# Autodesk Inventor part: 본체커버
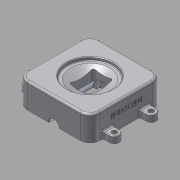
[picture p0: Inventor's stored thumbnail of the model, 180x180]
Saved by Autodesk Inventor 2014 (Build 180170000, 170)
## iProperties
Created: 2018-01
Part Number: 본체커버
Material: 알루미늄 6061
Document SubType Name: Modeling
Designer: mduedu
Density: 1 g/cm^3
Appearance: Aluminum - Flat
Author: mduedu
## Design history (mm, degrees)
sketch "스케치1"
  geometry: L1 (55, 55)-(-55, 55); L2 (-55, 55)-(-55, -55); L3 (-55, -55)-(55, -55); L4 (55, -55)-(55, 55); L5 (55, 55)-(-55, -55); L6 (-55, 55)-(55, -55); 1 further point
  constraints: 12 end point, 2 midpoint, 2 parallel, 1 horizontal, 1 perpendicular
  dimensions: "d0" = 110 distance of L3.end L2.end; "d1" = 110 distance of L2.end L1.end
extrude "돌출1" new body sketch "스케치1" distance "d2" = 38; taper "d3" = 0 deg
sketch "스케치2"
  geometry: L1 (-55, 55)-(55, 55) reference; L2 (-55, -55)-(-55, 55) reference; L3 (55, -55)-(-55, -55) reference; L4 (55, 55)-(55, -55) reference; L5 (0, 55)-(7.5, 55); L6 (7.5, 55)-(7.5, 36); L7 (7.5, 36)-(0, 36); L8 (0, 36)-(0, 55); L9 (0, 36)-(16, 36); L10 (16, 36)-(16, 22); L11 (16, 22)-(0, 22); L12 (0, 22)-(0, 36); L13 (0, 22)-(20, 22); L14 (20, 22)-(20, -25); L15 (20, -25)-(0, -25); L16 (0, -25)-(0, 22); L17 (0, -25)-(15, -25); L18 (15, -25)-(15, -30); L19 (15, -30)-(0, -30); L20 (0, -30)-(0, -25); 1 further point
  constraints: 32 end point, 8 parallel, 4 horizontal, 4 perpendicular, 1 midpoint
  dimensions: "d4" = 15 diameter of L6 L8; "d6" = 32 diameter of L10 L12; "d7" = 40 diameter of L14 L16; "d8" = 30 diameter of L18 L20; "d9" = 5 distance of L17.end L18.end; "d10" = 47 distance of L13.end L14.end; "d11" = 14 distance of L9.end L10.end; "d12" = 19 distance of L5.end L6.end
revolve "회전1" sketch "스케치2" stored, may be unused: angle "d13" = 90 deg
fillet "모깎기1" dims "d14" = 1
fillet "모깎기2" dims "d15" = 15
fillet "모깎기3" dims "d16" = 3
sketch "스케치3"
  geometry: L1 (-15, -17)-(15, -17); L2 (15, -17)-(15, 20); L3 (15, 20)-(-15, 20); L4 (-15, 20)-(-15, -17); L5 (-19, -22)-(19, -22) reference; L6 (19, 25)-(-19, 25) reference; 2 further points
  constraints: 8 end point, 2 parallel, 1 horizontal, 1 midpoint, 1 perpendicular, 1 vertical alignment
  dimensions: "d17" = 5 distance between parallel lines of L1 L5; "d18" = 5 distance between parallel lines of L6 L3; "d19" = 37 distance of L3.end L1.start (derived); "d20" = 30 distance between parallel lines of L2 L4
extrude "돌출2" cut sketch "스케치3" stored distance "d21" = 38; taper "d22" = 0 deg
fillet "모깎기4" dims "d23" = 3
sketch "스케치4"
  geometry: L1 (38, 35)-(33, 35); L2 (33, 35)-(33, 30); L3 (33, 30)-(26, 15); L4 (26, 15)-(26, 0); L5 (26, 0)-(38, 0); L6 (38, 0)-(38, 35); L7 (38, 40)-(38, -40) reference; 1 further point
  constraints: 12 end point, 2 parallel, 1 collinear, 1 horizontal, 1 horizontal alignment, 1 perpendicular
  dimensions: "d24" = 5 distance of L1.start L1.end; "d26" = 70 diameter of L1 L5; "d28" = 60 diameter of L2.end L5; "d29" = 30 diameter of L3.end L5; "d30" = 7 horizontal distance of L2.end L3.end
revolve "회전2" sketch "스케치4" stored, may be unused: angle "d31" = 90 deg
chamfer "모따기1" distance "d32" = 1; stored, may be unused: second distance "d33" = 2, angle "d34" = 45 deg
fillet "모깎기5" dims "d35" = 1
chamfer "모따기2" distance "d36" = 1; stored, may be unused: second distance "d37" = 2, angle "d38" = 45 deg
sketch "스케치5"
  geometry: L1 (7.5, 54)-(8.5, 55) reference; L2 (7.5, 54)-(7.5, 37) reference; L3 (8.5, 36)-(7.5, 37) reference; L4 (8.5, 36)-(15, 36) reference; L5 (16, 35)-(16, 22) reference; L6 (16, 22)-(19, 22) reference; L7 (20, 21)-(20, -24) reference; L8 (19, -25)-(15, -25) reference; L9 (15, -25)-(15, -29) reference; L10 (14, -30)-(-14, -30) reference; L11 (-15, -29)-(-15, -25) reference; L12 (-15, -25)-(-19, -25) reference; L13 (-20, -24)-(-20, 21) reference; L14 (-19, 22)-(-16, 22) reference; L15 (-16, 22)-(-16, 35) reference; L16 (-15, 36)-(-8.5, 36) reference; L17 (-7.5, 37)-(-8.5, 36) reference; L18 (-7.5, 37)-(-7.5, 54) reference; L19 (-8.5, 55)-(-7.5, 54) reference; L20 (-40, 55)-(-8.5, 55) reference; L21 (-55, -40)-(-55, 40) reference; L22 (40, -55)-(-40, -55) reference; L23 (55, 40)-(55, -40) reference; L24 (8.5, 55)-(40, 55) reference; L25 (55, 35.5)-(65, 35.5); L26 (65, 20.5)-(55, 20.5); L27 (55, 20.5)-(55, 35.5); L28 (55, 40)-(55, -40) reference; A1 r 1 centre (15, 35) between (16, 35) and (15, 36) reference; A2 r 1 centre (19, 21) between (20, 21) and (19, 22) reference; A3 r 1 centre (19, -24) between (19, -25) and (20, -24) reference; A4 r 1 centre (14, -29) between (14, -30) and (15, -29) reference; A5 r 1 centre (-14, -29) between (-15, -29) and (-14, -30) reference; A6 r 1 centre (-19, -24) between (-20, -24) and (-19, -25) reference; A7 r 1 centre (-19, 21) between (-19, 22) and (-20, 21) reference; A8 r 1 centre (-15, 35) between (-15, 36) and (-16, 35) reference; A9 r 15 centre (-40, 40) between (-40, 55) and (-55, 40) reference; A10 r 15 centre (-40, -40) between (-55, -40) and (-40, -55) reference; A11 r 15 centre (40, -40) between (40, -55) and (55, -40) reference; A12 r 15 centre (40, 40) between (55, 40) and (40, 55) reference; A13 r 7.5 centre (65, 28) between (65, 20.5) and (65, 35.5); 1 further point
  constraints: 6 end point, 2 point on circle, 2 tangent, 1 centre point, 1 collinear, 1 horizontal, 1 parallel, 1 point on line
  dimensions: "d39" = 15 distance between parallel lines of L26 L25; "d41" = 28 vertical distance of A13.centre point (0, 0); "d42" = 10 distance from line of A13.centre L23
extrude "돌출3" join sketch "스케치5" distance "d43" = 10; taper "d44" = 0 deg
fillet "모깎기6" dims "d45" = 1
fillet "모깎기7" dims "d46" = 3
sketch "스케치6"
  geometry: A1 r 7.5 centre (-65, 28) between (-65, 35.5) and (-65, 20.5) reference; A2 r 7.5 centre (-65, -28) between (-65, -20.5) and (-65, -35.5) reference; A3 r 7.5 centre (65, -28) between (65, -35.5) and (65, -20.5) reference; A4 r 7.5 centre (65, 28) between (65, 20.5) and (65, 35.5) reference; 5 further points
  constraints: 4 coincident
sketch "스케치7"
  geometry: 4 further points
  constraints: 4 other
hole "구멍1" sketch "스케치7" at (-65, 28), (65, 28), (-65, -28), (65, -28) diameter "d47" = 4.5; stored, may be unused: countersink angle "d51" = 90 deg, drill point angle "d53" = 0 deg; dims "d48" = 6, "d49" = 8, "d50" = 4.6, "d52" = 8
sketch "스케치8"
  geometry: L1 (-95, 35)-(-95, 0) reference; L2 (0, 38)-(-80, 38) reference; 2 further points
  constraints: 1 other
  dimensions: "d54" = 55 distance from line of point (-40, 23) L1; "d55" = 15 distance from line of point (-40, 23) L2
feature "엠보싱1" sketch "스케치8" dims "d0" = 110, "d1" = 110, "d56" = 0.5, "d57" = 0
node "솔리드1"
mirror "대칭1"
mirror "대칭2"
node "투영된 루프1"
node "투영된 루프2"
